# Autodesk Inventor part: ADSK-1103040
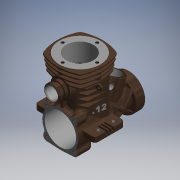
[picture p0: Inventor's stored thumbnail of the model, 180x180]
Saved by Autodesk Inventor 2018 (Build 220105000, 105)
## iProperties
Shininess: 11.0
Compacted: True
Length Units: 11269
Angle Units: 11279
Time Units: 11290
Mass Units: 11286
Length Display Precision: 2
Angle Display Precision: 2
Created: 2000-07
Part Number: ADSK-1103040
Document SubType Name: Modeling
Description: ENGINE  CASE - REAR
Mass: 106.427 g
Surface Area: 158.116 cm^2
Volume: 13.1716 cm^3
Density: 8.08 g/cm^3
Material: Stainless Steel
Appearance: Bronze - Satin
Density: 0.0
Volumn: 0.0
Area: 0.0
PropertySet Name: Model Information
Control State: 0
Master: False
Checked Out: False
Author: Autodesk, Inc.
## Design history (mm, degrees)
node "Extrusion1" dims "d2" = 3.5, "d3" = 0
  sketch "Sketch2"
    geometry: L1 (-28.715, -16.977)-(11.285, -16.977); L2 (11.285, -16.977)-(11.285, 3.023); L3 (11.285, 3.023)-(-28.715, 3.023); L4 (-28.715, 3.023)-(-28.715, -16.977)
    constraints: 8 end point, 2 parallel, 1 horizontal, 1 perpendicular
    dimensions: "d0" = 40 distance of L2.end L3.end; "d1" = 20 distance of L3.end L1.start
workplane "Work Plane1"
workplane "Work Plane2"
node "Extrusion2" dims "d6" = 25.5, "d7" = 0
  sketch "Sketch3"
    geometry: L1 (20, -16.8)-(20, 16.8) reference; L2 (0, 0)-(40, 0) reference; C1 r 12 at (20, 0)
    constraints: 1 centre point, 1 midpoint
    dimensions: "d5" = 24 diameter of C1
node "Extrusion3" dims "d13" = 25, "d14" = 0
  sketch "Sketch4"
    geometry: L1 (-20.715, 3.023)-(3.285, 3.023); L2 (-2.715, -16.977)-(-14.715, -16.977); L3 (-8.715, -21.506)-(-8.715, 7.111) reference; L4 (-28.715, -16.977)-(-20.715, -16.977) reference; A1 r 36.333 centre (-33.049, 3.023) between (-2.715, -16.977) and (3.285, 3.023); A2 r 36.333 centre (15.618, 3.023) between (-20.715, 3.023) and (-14.715, -16.977)
    constraints: 4 end point, 4 point on circle, 2 centre point, 2 point on line, 1 collinear, 1 horizontal
    dimensions: "d8" = 24 distance of L1.start L1.end; "d9" = 12 distance of L2.start L2.end; "d10" = 6 distance from line of L3 L2.start (= 0.5 x d9); "d11" = 12 distance from line of L1.end L3 (= 0.5 x d8); "d12" = 20 distance between parallel lines of L2 L1
node "Extrusion5" dims "d18" = 14, "d19" = 0
  sketch "Sketch6"
    geometry: C1 r 11.33 at (0, 0); C2 r 8 at (0, 0); C3 r 12 at (0, 0) reference
    constraints: 2 centre point, 1 coincident
    dimensions: "d17" = 16 diameter of C2
workplane "Work Plane15"
node "Extrusion6" dims "d21" = 6, "d22" = 0
  sketch "Sketch7"
    geometry: C1 r 7.5 at (0, 0); C2 r 11 at (0, 0)
    constraints: 2 centre point, 1 coincident
    dimensions: "d20" = 22 diameter of C2
fillet "Fillet48" dims "d248" = 2
fillet "Fillet53" dims "d264" = 2, "d265" = 1
feature "LoftSrf2" dims "d266" = 0, "d267" = 90 deg, "d268" = 0, "d269" = 90 deg
  node "Edges3"
  node "Edges4"
feature "OffsetSrf1" dims "d270" = 1, "d271" = 1
node "Revolution1" dims "d28" = 90 deg
  sketch "Sketch10"
    geometry: L1 (-20, -3.5)-(0, -3.5) reference; L2 (-20.351, 1.344)-(-25.14, 14.5); L3 (-25.14, 14.5)-(-31.718, 12.106); L4 (-31.718, 12.106)-(-26.929, -1.05); L5 (-26.929, -1.05)-(-20.351, 1.344); L6 (-22.5, 4.5)-(-36.5, 4.5) reference; L7 (-22.5, -15.5)-(-22.5, 8.5) reference; 1 further point
    constraints: 8 end point, 2 perpendicular, 2 point on line, 1 parallel
    dimensions: "d26" = 70 deg angle of L1 L2; "d27" = 14 diameter of L2 L4; "d231" = 14 distance of L2.start L2.end; "d241" = 10 distance from line of L6 L2.end; "d242" = 1 distance from line of L7 point (-21.5, 4.5)
workplane "Work Plane3"
  workaxis "Work Axis1"
workaxis "Work Axis2"
workplane "Work Plane5"
workplane "Work Plane30"
node "Extrusion12" dims "d54" = 8, "d55" = 0
  sketch "Sketch15"
    geometry: L1 (-9, 9)-(9, 9); L2 (9, 9)-(9, -9); L3 (9, -9)-(-9, -9); L4 (-9, -9)-(-9, 9); C1 r 12 at (0, 0) reference; C2 r 2.5 at (-9, 9); C3 r 2.5 at (9, 9); C4 r 2.5 at (9, -9); C5 r 2.5 at (-9, -9)
    constraints: 8 end point, 4 centre point, 4 coincident, 3 equal radius, 2 parallel, 2 perpendicular, 1 horizontal
    dimensions: "d50" = 18 distance of L2.end L3.end; "d51" = 9 distance from line of C1.centre L4 (= 0.5 x d50); "d52" = 9 distance from line of C1.centre L3 (= d51); "d53" = 5 diameter of C3
node "Extrusion13" dims "d56" = 8, "d57" = 0
  sketch "Sketch16"
    geometry: L1 (10.857, -11.496)-(19.314, -11.98); L2 (29.143, -11.496)-(20.686, -11.98); A1 r 2.5 centre (11, -9) between (10.039, -6.692) and (13.308, -9.961) reference; A2 r 12 centre (20, 0) between (13.308, -9.961) and (26.692, -9.961) reference; A3 r 2.5 centre (29, -9) between (26.692, -9.961) and (29.961, -6.692) reference
    constraints: 4 end point, 4 point on circle, 4 tangent
node "Fillet1" dims "d58" = 2.5
node "Fillet3" dims "d60" = 5
node "Fillet4" dims "d61" = 3
node "Fillet5" dims "d62" = 2
node "Revolution2" dims "d63" = 180 deg
  sketch "Sketch17"
    geometry: L1 (0.686, 11.98)-(9.143, 11.496) reference; L2 (9.143, 11.496)-(0.686, 11.98); L3 (0.686, 11.98)-(0.543, 9.484); L4 (0.543, 9.484)-(9, 9); L5 (9, 9)-(9.143, 11.496); L6 (9, 9)-(11.496, 8.857); A1 r 12 centre (0, 0) between (9.961, 6.692) and (0.686, 11.98) reference; A2 r 2.5 centre (9, 9) between (9.961, 6.692) and (9.143, 11.496) reference
    constraints: 10 end point, 3 equal length, 2 perpendicular, 2 tangent, 1 point on circle, 1 point on line
node "Mirror2"
node "Fillet6" dims "d64" = 2.5
node "Fillet8" dims "d66" = 3.5
node "Fillet17" dims "d75" = 2
node "Fillet18" dims "d76" = 0.3
node "Fillet19" dims "d77" = 0.5
node "Extrusion14" dims "d84" = 9, "d85" = 0
  sketch "Sketch18"
    geometry: L1 (-17.028, 3.023)-(-0.402, 3.023) reference; L2 (-8.715, -25.077)-(-8.715, 10.623) reference; C1 r 10.018 at (-8.715, -6.996); A1 r 36.333 centre (15.618, 3.023) between (-20.508, -0.85) and (-16.281, -14.371) reference
    constraints: 2 tangent, 1 centre point, 1 point on line
node "Extrusion15" dims "d90" = 1, "d91" = 0
  sketch "Sketch19"
    geometry: L1 (5.035, 6.754)-(-22.465, 6.754); L2 (-22.465, 6.754)-(-22.465, -20.746); L3 (-22.465, -20.746)-(5.035, -20.746); L4 (5.035, -20.746)-(5.035, 6.754); A1 r 10.018 centre (-8.715, -6.996) between (0.549, -10.81) and (-8.715, 3.023) reference; A2 r 27.5 centre (-22.465, -6.996) between (2.599, -18.31) and (2.599, 4.319); A3 r 27.5 centre (5.035, -6.996) between (-20.03, 4.319) and (-20.03, -18.31); A4 r 27.5 centre (-8.715, 6.754) between (-20.03, -18.31) and (2.599, -18.31); A5 r 27.5 centre (-8.715, -20.746) between (2.599, 4.319) and (-20.03, 4.319); A6 r 29.032 centre (-8.715, -20.746) between (-22.465, 4.823) and (-23.458, 4.264)
    constraints: 12 point on circle, 8 end point, 5 centre point, 3 midpoint, 3 tangent, 2 parallel, 2 perpendicular, 1 horizontal, 1 point on line
    dimensions: "d86" = 27.5 distance of L2.end L3.end; "d87" = 13.75 distance from line of L4 A1.centre (= 0.5 x d86); "d88" = 13.75 distance from line of L3 A1.centre (= d87); "d89" = 13.75 distance from line of L2 A4.centre (= d87)
node "Fillet26" dims "d92" = 2
workplane "Work Plane6"
node "Extrusion16" dims "d95" = 1, "d96" = 0
  sketch "Sketch20"
    geometry: A1 r 27.5 centre (-8.715, -20.746) between (1.847, 4.645) and (-19.278, 4.645) reference; A2 r 27.5 centre (5.035, -6.996) between (-20.356, 3.567) and (-20.356, -17.558) reference; A3 r 2 centre (-18.509, 2.798) between (-19.278, 4.645) and (-20.356, 3.567) reference; A4 r 2 centre (1.079, 2.798) between (2.925, 3.567) and (1.847, 4.645) reference; A5 r 27.5 centre (-22.465, -6.996) between (2.925, -17.558) and (2.925, 3.567) reference; A6 r 2 centre (1.079, -16.79) between (1.847, -18.636) and (2.925, -17.558) reference; A7 r 27.5 centre (-8.715, 6.754) between (-19.278, -18.636) and (1.847, -18.636) reference; A8 r 2 centre (-18.509, -16.79) between (-20.356, -17.558) and (-19.278, -18.636) reference; A9 r 28 centre (-8.715, -20.746) between (2.039, 5.107) and (-19.47, 5.107); A10 r 2.5 centre (1.079, 2.798) between (3.387, 3.759) and (2.039, 5.107); A11 r 28 centre (-22.465, -6.996) between (3.387, -17.75) and (3.387, 3.759); A12 r 2.5 centre (1.079, -16.79) between (2.039, -19.098) and (3.387, -17.75); A13 r 28 centre (-8.715, 6.754) between (-19.47, -19.098) and (2.039, -19.098); A14 r 2.5 centre (-18.509, -16.79) between (-20.818, -17.75) and (-19.47, -19.098); A15 r 28 centre (5.035, -6.996) between (-20.818, 3.759) and (-20.818, -17.75); A16 r 2.5 centre (-18.509, 2.798) between (-19.47, 5.107) and (-20.818, 3.759)
    constraints: 16 point on circle, 8 centre point, 7 other
    dimensions: "d94" = 0.5 radial gap between concentric circles of A9 A1
workplane "Work Plane7"
node "Extrusion17" dims "d99" = 1, "d100" = 0
  sketch "Sketch21"
    geometry: A1 r 28 centre (-8.715, -20.746) between (2.039, 5.107) and (-19.47, 5.107) reference; A2 r 28 centre (5.035, -6.996) between (-20.818, 3.759) and (-20.818, -17.75) reference; A3 r 2.5 centre (-18.509, -16.79) between (-20.818, -17.75) and (-19.47, -19.098) reference; A4 r 2.5 centre (-18.509, 2.798) between (-19.47, 5.107) and (-20.818, 3.759) reference; A5 r 28 centre (-8.715, 6.754) between (-19.47, -19.098) and (2.039, -19.098) reference; A6 r 2.5 centre (1.079, -16.79) between (2.039, -19.098) and (3.387, -17.75) reference; A7 r 28 centre (-22.465, -6.996) between (3.387, -17.75) and (3.387, 3.759) reference; A8 r 2.5 centre (1.079, 2.798) between (3.387, 3.759) and (2.039, 5.107) reference; A9 r 28.5 centre (-8.715, -20.746) between (2.231, 5.568) and (-19.662, 5.568); A10 r 3 centre (1.079, 2.798) between (3.849, 3.951) and (2.231, 5.568); A11 r 28.5 centre (-22.465, -6.996) between (3.849, -17.942) and (3.849, 3.951); A12 r 3 centre (1.079, -16.79) between (2.231, -19.56) and (3.849, -17.942); A13 r 28.5 centre (-8.715, 6.754) between (-19.662, -19.56) and (2.231, -19.56); A14 r 3 centre (-18.509, -16.79) between (-21.279, -17.942) and (-19.662, -19.56); A15 r 28.5 centre (5.035, -6.996) between (-21.279, 3.951) and (-21.279, -17.942); A16 r 3 centre (-18.509, 2.798) between (-19.662, 5.568) and (-21.279, 3.951)
    constraints: 16 point on circle, 8 centre point, 7 other
    dimensions: "d98" = 0.5 radial gap between concentric circles of A9 A1
workplane "Work Plane8"
node "Extrusion18" dims "d103" = 1, "d104" = 0
  sketch "Sketch22"
    geometry: A1 r 28.5 centre (-8.715, -20.746) between (2.231, 5.568) and (-19.662, 5.568) reference; A2 r 3 centre (-18.509, 2.798) between (-19.662, 5.568) and (-21.279, 3.951) reference; A3 r 28.5 centre (5.035, -6.996) between (-21.279, 3.951) and (-21.279, -17.942) reference; A4 r 3 centre (-18.509, -16.79) between (-21.279, -17.942) and (-19.662, -19.56) reference; A5 r 28.5 centre (-8.715, 6.754) between (-19.662, -19.56) and (2.231, -19.56) reference; A6 r 3 centre (1.079, -16.79) between (2.231, -19.56) and (3.849, -17.942) reference; A7 r 28.5 centre (-22.465, -6.996) between (3.849, -17.942) and (3.849, 3.951) reference; A8 r 3 centre (1.079, 2.798) between (3.849, 3.951) and (2.231, 5.568) reference; A9 r 29 centre (-8.715, -20.746) between (2.423, 6.03) and (-19.854, 6.03); A10 r 3.5 centre (1.079, 2.798) between (4.31, 4.143) and (2.423, 6.03); A11 r 29 centre (-22.465, -6.996) between (4.31, -18.134) and (4.31, 4.143); A12 r 3.5 centre (1.079, -16.79) between (2.423, -20.021) and (4.31, -18.134); A13 r 29 centre (-8.715, 6.754) between (-19.854, -20.021) and (2.423, -20.021); A14 r 3.5 centre (-18.509, -16.79) between (-21.741, -18.134) and (-19.854, -20.021); A15 r 29 centre (5.035, -6.996) between (-21.741, 4.143) and (-21.741, -18.134); A16 r 3.5 centre (-18.509, 2.798) between (-19.854, 6.03) and (-21.741, 4.143)
    constraints: 16 point on circle, 8 centre point, 7 other
    dimensions: "d102" = 0.5 radial gap between concentric circles of A9 A1
node "Extrusion19" dims "d108" = 1, "d109" = 0
  sketch "Sketch23" dims "d105" = 23
    geometry: L1 (-8.715, -31.799)-(-8.715, 35.076) reference; C1 r 10.018 at (-8.715, -6.996) reference; A1 r 2 centre (-8.715, 4.504) between (-6.717, 4.422) and (-10.714, 4.422); A2 r 2 centre (-4.719, 4.339) between (-6.717, 4.422) and (-5.384, 2.453); A3 r 2 centre (-12.712, 4.339) between (-12.047, 2.453) and (-10.714, 4.422); A4 r 10.018 centre (-8.715, -6.996) between (-5.384, 2.453) and (-12.047, 2.453); 1 further point
    constraints: 8 point on circle, 4 centre point, 4 tangent, 2 equal radius, 1 coincident, 1 concentric, 1 point on line, 1 vertical alignment, 2 other
    dimensions: "d106" = 4 diameter of A1; "d107" = 2 radius of A2
workaxis "Work Axis3"
node "Circular Pattern2" dims "d110" = 40, "d112" = 360 deg
node "Fillet27" dims "d113" = 0.3
node "Fillet28" dims "d114" = 0.5
workplane "Work Plane9"
node "Fillet34" dims "d130" = 0.45
sketch "Sketch47"
  geometry: L1 (0, 8.296)-(0, -10.725)
  constraints: 2 end point, 1 vertical
feature "Rib1" sketch "Sketch47" dims "d246" = 2, "d247" = 1
fillet "Fillet49" dims "d249" = 1
fillet "Fillet50" dims "d250" = 1
fillet "Fillet51" dims "d251" = 1
fillet "Fillet52" dims "d252" = 1
workplane "Work Plane17"
split "Split2"
sketch "Sketch51"
  geometry: L1 (-37.441, 3.747)-(-20.441, -10.747); L2 (-37.441, -10.747)-(-20.441, 3.747); L3 (-37.441, 4.569)-(-37.441, 2.926); L4 (-37.441, 2.926)-(-29.905, -3.5); L5 (-29.905, -3.5)-(-37.441, -9.926); L6 (-37.441, -9.926)-(-37.441, -11.569); L7 (-37.441, -11.569)-(-28.941, -4.321); L8 (-28.941, -4.321)-(-20.441, -11.569); L9 (-20.441, -11.569)-(-20.441, -9.926); L10 (-20.441, -9.926)-(-27.978, -3.5); L11 (-27.978, -3.5)-(-20.441, 2.926); L12 (-20.441, 2.926)-(-20.441, 4.569); L13 (-20.441, 4.569)-(-28.941, -2.679); L14 (-28.941, -2.679)-(-37.441, 4.569); L15 (-37.441, -13.502)-(-37.441, 6.502) reference; L16 (-20.441, -14.502)-(-20.441, 7.502) reference; 2 further points
  constraints: 28 end point, 12 collinear, 8 parallel, 6 midpoint, 2 horizontal alignment, 1 vertical
  dimensions: "d272" = 1.25 distance between parallel lines of L14 L4
extrude "Extrusion38" join sketch "Sketch51" stored distance "d273" = 14; taper "d274" = 0 deg
mirror "Mirror3"
fillet "Fillet54" dims "d275" = 1
fillet "Fillet58" dims "d279" = 10
fillet "Fillet55" dims "d276" = 0.3
fillet "Fillet57" dims "d278" = 0.3
node "Hole1" dims "d139" = 2.013, "d140" = 4, "d141" = 2, "d142" = 60 deg, "d143" = 5, "d144" = 118 deg
  sketch "Sketch28"
    geometry: A1 r 2.5 centre (29, 9) between (30.967, 7.457) and (27.457, 10.967) reference; A2 r 2.5 centre (11, 9) between (12.543, 10.967) and (9.033, 7.457) reference; A3 r 2.5 centre (11, -9) between (8.939, -7.585) and (10.857, -11.496) reference; A4 r 2.5 centre (29, -9) between (29.143, -11.496) and (31.061, -7.585) reference
node "Extrusion24" dims "d152" = 25, "d153" = 0
  sketch "Sketch30"
    geometry: C1 r 9 at (-8.715, -6.996); A1 r 10.518 centre (-8.715, -6.996) between (-18.635, -10.493) and (-12.213, -16.915) reference
    constraints: 1 centre point, 1 coincident
    dimensions: "d151" = 18 diameter of C1
node "Extrusion25" dims "d154" = 0.25, "d155" = 0
  sketch "Sketch31"
    geometry: C1 r 9 at (-8.715, -6.996) reference; A1 r 28.7 centre (-8.715, 6.754) between (-19.739, -19.744) and (2.308, -19.744) reference; 1 further point
    constraints: 1 coincident, 1 vertical alignment, 2 other
workaxis "Work Axis8"
workplane "Work Plane33"
node "Fillet38" dims "d156" = 0.5
node "Hole3" dims "d157" = 2.013, "d158" = 4, "d159" = 2, "d160" = 60 deg, "d161" = 8, "d162" = 118 deg
  sketch "Sketch32"
    geometry: A1 r 2.5 centre (-8.715, 4.504) between (-6.218, 4.401) and (-11.213, 4.401) reference; 2 further points
node "Circular Pattern3" dims "d163" = 40, "d165" = 360 deg
workplane "Work Plane10"
node "Extrusion26" dims "d172" = 1, "d173" = 0
  sketch "Sketch33"
    geometry: L1 (20.526, -0.599)-(20.124, -12.117); L2 (18.879, -14.443)-(13.845, -16.58); L3 (15.656, -15.268)-(18.907, -13.888); L4 (0.402, 3.023)-(17.028, 3.023) reference; A1 r 36.333 centre (-15.618, 3.023) between (16.281, -14.371) and (20.508, -0.85) reference; A2 r 3.5 centre (17.028, -0.477) between (20.508, -0.85) and (17.028, 3.023) reference; A3 r 5 centre (11.892, -11.977) between (11.892, -16.977) and (16.281, -14.371) reference; A4 r 2 centre (18.125, -12.047) between (18.907, -13.888) and (20.124, -12.117)
    constraints: 6 end point, 5 point on circle, 4 tangent, 1 centre point, 1 parallel
    dimensions: "d168" = 115 deg angle of L2 L1; "d170" = 2 radius of A4; "d171" = 0.5 distance between parallel lines of L2 L3; "d280" = 88 deg angle of L4 L1
node "Fillet39" dims "d174" = 0.3
mirror "Mirror4"
fillet "Fillet59" dims "d281" = 0.5
node "Rectangular Pattern1" dims "d176" = 40, "d178" = 3.5
node "Extrusion27" dims "d180" = 4, "d181" = 0
  sketch "Sketch34"
    geometry: C1 r 11 at (0, 0); C2 r 8 at (0, 0); A1 r 11 centre (0, 0) between (-11, 0) and (11, 0) reference; A2 r 11 centre (0, 0) between (11, 0) and (-11, 0) reference
    constraints: 2 centre point, 1 coincident
    dimensions: "d179" = 16 diameter of C2
node "Extrusion28" dims "d183" = 4, "d184" = 0
  sketch "Sketch35"
    geometry: C1 r 8 at (0, 0) reference; C2 r 6 at (0, 0)
    constraints: 1 centre point, 1 coincident
    dimensions: "d182" = 12 diameter of C2
node "Extrusion29" dims "d186" = 20, "d187" = 0
  sketch "Sketch36"
    geometry: C1 r 10.5 at (20, 0); A1 r 12 centre (20, 0) between (30.859, -5.106) and (30.749, 5.334) reference
    constraints: 1 centre point, 1 coincident
    dimensions: "d185" = 21 diameter of C1
node "Extrusion30" dims "d189" = 22, "d190" = 0
  sketch "Sketch37"
    geometry: C1 r 7 at (-8.715, -6.996); A1 r 13.75 centre (-8.715, -6.996) between (5.035, -6.996) and (-22.465, -6.996) reference
    constraints: 1 centre point, 1 coincident
    dimensions: "d188" = 14 diameter of C1
sketch "Sketch43"
  geometry: L1 (12.324, 33.859)-(-10.939, -30.056); L2 (1.197, 3.289)-(-5.381, 5.683); L3 (-4.342, 9.03)-(5.376, 5.493); L4 (17.596, 48.345)-(-18.614, -51.141) reference; L5 (-8.665, 10.603)-(-8.323, 10.479) reference; L6 (-8.323, 10.479)-(-4.885, 9.227) reference; L7 (-3.975, 8.896)-(-4.885, 9.227) reference; L8 (-3.975, 8.896)-(-3.975, 8.896) reference; L9 (-4.885, 9.227)-(-3.975, 8.896) reference; L10 (-4.885, 9.227)-(-8.323, 10.479) reference; L11 (-8.665, 10.603)-(-8.323, 10.479) reference; C1 r 2.75 at (-5.381, 5.683)
  constraints: 6 end point, 2 collinear, 1 centre point, 1 coincident, 1 perpendicular, 1 point on line
  dimensions: "d216" = 7 distance of L2.start L2.end; "d217" = 3.5 distance between parallel lines of L2 L3; "d218" = 5.5 diameter of C1
extrude "Extrusion39" join sketch "Sketch43" distance "d282" = 14; taper "d283" = 0 deg
fillet "Fillet60" dims "d284" = 0.5
node "Extrusion35" dims "d223" = 15, "d224" = 0
  sketch "Sketch44"
    geometry: C1 r 5.5 at (0, 0); A1 r 7 centre (0, 0) between (1.75, -6.778) and (-1.75, -6.778) reference
    constraints: 1 centre point, 1 concentric
    dimensions: "d222" = 11 diameter of C1
node "Extrusion36" dims "d226" = 15, "d227" = 0
  sketch "Sketch45"
    geometry: C1 r 2.75 at (0, 0); C2 r 2 at (0, 0); C3 r 2.75 at (0, 0) reference
    constraints: 2 centre point, 1 coincident
    dimensions: "d225" = 4 diameter of C2
node "Chamfer1" dims "d228" = 0.5, "d229" = 0.5, "d239" = 45 deg
node "Hole4" dims "d233" = 2.5, "d234" = 4, "d235" = 2, "d236" = 60 deg, "d237" = 8, "d238" = 118 deg
  sketch "Sketch46"
    geometry: C1 r 1.078 at (8.285, -11.027) reference; C2 r 1.078 at (8.285, -1.027) reference; C3 r 1.078 at (-25.715, -1.977) reference; C4 r 1.078 at (-25.715, -11.977) reference
sketch "Sketch52"
  geometry: L1 (1.337, 11.656)-(8.684, 11.656); L2 (8.684, 11.656)-(8.684, 8.517); L3 (8.684, 8.517)-(1.337, 8.517); L4 (1.337, 8.517)-(1.337, 11.656)
  constraints: 2 other
emboss "Emboss1" sketch "Sketch52" dims "d288" = 0.333, "d289" = 0
sketch "Sketch53"
  geometry: L1 (-11.887, 5.713)-(-11.887, 13.872); L2 (-11.887, 13.872)-(-8.327, 13.872); L3 (-8.327, 13.872)-(-8.327, 5.713); L4 (-8.327, 5.713)-(-11.887, 5.713)
  constraints: 2 other
emboss "Emboss2" sketch "Sketch53" dims "d293" = 0.33, "d294" = 0
fillet "Fillet77" dims "d396" = 0.25
fillet "Fillet78" dims "d397" = 0.1
fillet "Fillet79" dims "d398" = 0.25
fillet "Fillet80" dims "d399" = 0.1
split "Split4"
split "Split7"
sketch "Sketch54"
  geometry: L1 (-37.441, -13.502)-(-20.441, -14.502) reference; L2 (-34.186, -13.693)-(-24.164, -14.283); L3 (11.1, -3.5)-(-45.6, -3.5) reference; A1 r 1 centre (-37.5, -13.5) between (-37.5, -14.5) and (-36.5, -13.5) reference; A2 r 2 centre (-20.5, -13.5) between (-22.5, -13.5) and (-20.5, -15.5) reference; A3 r 1 centre (-37.5, -13.5) between (-37.5, -14.5) and (-36.997, -14.364); A4 r 2 centre (-20.5, -13.5) between (-21.631, -15.15) and (-20.5, -15.5); A5 r 5 centre (-34.48, -18.685) between (-34.186, -13.693) and (-36.997, -14.364); A6 r 5 centre (-24.457, -19.274) between (-21.631, -15.15) and (-24.164, -14.283)
  constraints: 10 point on circle, 5 tangent, 4 centre point, 3 equal radius, 2 end point, 1 collinear, 1 point on line
  dimensions: "d295" = 5 radius of A5
feature "RevolutionSrf1" sketch "Sketch54" dims angle "d328" = 10 deg
thicken "Thicken1" dims "d329" = 3, "d330" = 4
node "Extrusion31" dims "d192" = 5, "d193" = 0
  sketch "Sketch38"
    geometry: C1 r 10.5 at (0, 0) reference; C2 r 9.5 at (0, 0)
    constraints: 1 centre point, 1 coincident
    dimensions: "d191" = 19 diameter of C2
fillet "Fillet64" dims "d331" = 0.5
fillet "Fillet65" dims "d332" = 0.5
workplane "Work Plane29"
workplane "Work Plane31"
workaxis "Work Axis7"
sketch "Sketch55"
  geometry: C1 r 6.5 at (0, 23.5); 1 further point
  constraints: 1 centre point, 1 coincident
  dimensions: "d336" = 13 diameter of C1
extrude "Extrusion40" join sketch "Sketch55" stored distance "d337" = 10; taper "d338" = 0 deg
sketch "Sketch57"
  geometry: L1 (2.25, 9.25)-(2.25, 8.75); L2 (3, 1.834)-(3, -8.606) reference; L3 (3, 8.5)-(2, 8.5) reference
  constraints: 2 end point, 1 vertical
  dimensions: "d389" = 0.75 distance between parallel lines of L2 L1; "d390" = 0.25 distance from line of L3 L1.end; "d391" = 0.5 distance of L1.start L1.end
feature "Rib5" sketch "Sketch57" dims "d341" = 1, "d342" = 2
fillet "Fillet66" dims "d343" = 0.5
fillet "Fillet67" dims "d394" = 0.4
fillet "Fillet68" dims "d347" = 0.5
sketch "Sketch58"
  geometry: C1 r 6.5 at (0, 0) reference; C2 r 5.25 at (0, 0); C3 r 7.516 at (0, 0); 2 further points
  constraints: 2 centre point, 2 coincident, 1 horizontal alignment
  dimensions: "d348" = 1.25 radial gap between concentric circles of C2 C1
extrude "Extrusion41" cut sketch "Sketch58" distance "d349" = 6 (derived); taper "d350" = 0 deg
hole "Hole5" diameter "d353" = 8; stored, may be unused: countersink angle "d357" = 90 deg, drill point angle "d359" = 118 deg; dims "d351" = 10, "d352" = 10, "d354" = 6, "d355" = 4, "d356" = 2, "d358" = 8
chamfer "Chamfer2" distance "d360" = 0.5; stored, may be unused: second distance "d361" = 2, angle "d362" = 45 deg
fillet "Fillet76" dims "d393" = 0.5
sketch "Sketch59"
  geometry: L1 (12.125, 12.4)-(12.125, 12.5); L2 (15.875, 12.5)-(15.875, 12.4); A1 r 1.875 centre (14, 12.5) between (15.875, 12.5) and (12.125, 12.5); 1 further point
  constraints: 4 end point, 2 parallel, 2 point on circle, 2 tangent, 1 centre point, 1 vertical, 1 vertical alignment
  dimensions: "d364" = 1.875 radius of A1; "d365" = 12.5 distance of point (14, 0) A1.centre; "d366" = 0.1 distance of L1.start L1.end
extrude "Extrusion42" join sketch "Sketch59" distance "d368" = 1.5; taper "d369" = 0 deg
hole "Hole6" diameter "d372" = 1.5; stored, may be unused: countersink angle "d376" = 90 deg, drill point angle "d378" = 118 deg; dims "d370" = 10, "d371" = 10, "d373" = 6, "d374" = 4, "d375" = 2, "d377" = 8
fillet "Fillet69" dims "d379" = 0.5
mirror "Mirror5"
fillet "Fillet70" dims "d380" = 0.5
fillet "Fillet71" dims "d381" = 0.3
workplane "Work Plane34"
sketch "Sketch60"
  geometry: L1 (11.964, 9.428)-(11.964, 10.362); L2 (11.964, 10.362)-(29.739, 10.362); L3 (-10.2, 0)-(59.45, 0) reference
  constraints: 4 end point, 1 parallel, 1 perpendicular, 1 vertical
revolve "Revolution3" sketch "Sketch60" stored, may be unused: angle "d384" = 45 deg
fillet "Fillet72" dims "d385" = 2
fillet "Fillet73" dims "d386" = 1
mirror "Mirror6"
fillet "Fillet74" dims "d387" = 2
fillet "Fillet75" dims "d388" = 1
sketch "Sketch61" dims "d405" = 10
  geometry: L1 (3.2, 16)-(3.2, 0) reference; L2 (3.5, 10.482)-(1.5, 10.482); L3 (1.5, 10.482)-(1.5, 9.482); L4 (1.5, 9.482)-(3.5, 9.482); L5 (3.5, 9.482)-(3.5, 10.482); L6 (3.5, 8.482)-(1.5, 8.482); L7 (1.5, 8.482)-(1.5, 7.482); L8 (1.5, 7.482)-(3.5, 7.482); L9 (3.5, 7.482)-(3.5, 8.482); L10 (3.5, 6.482)-(1.5, 6.482); L11 (1.5, 6.482)-(1.5, 5.482); L12 (1.5, 5.482)-(3.5, 5.482); L13 (3.5, 5.482)-(3.5, 6.482); L14 (47.7, 7.982)-(-21.95, 7.982) reference; L15 (3.5, 0)-(3.5, 16) reference
  constraints: 24 end point, 6 parallel, 3 perpendicular, 1 collinear, 1 horizontal, 1 vertical, 17 other
  dimensions: "d402" = 2 distance of L2.start L6.start; "d407" = 1 distance of L4.end L2.start; "d408" = 2 distance of L2.start L2.end
extrude "Extrusion43" cut sketch "Sketch61" distance "d409" = 6; taper "d410" = 0 deg
fillet "Fillet81" dims "d411" = 0.5
mirror "Mirror7"
sketch "Sketch62"
  geometry: L1 (8.5, 25.25)-(3, 25.25) reference; L2 (3, 23.411)-(3, 13.5) reference; L3 (5, 25.25)-(6.5, 25.25); L4 (6.5, 25.25)-(6.5, 24.5); L5 (6.5, 24.5)-(5, 24.5); L6 (5, 24.5)-(5, 25.25); L7 (9, 24.75)-(9, 15.25) reference; L8 (9, 20)-(8.345, 20)
  constraints: 10 end point, 2 parallel, 2 perpendicular, 1 horizontal, 1 midpoint, 1 point on line
  dimensions: "d422" = 0.75 distance of L3.end L4.end; "d423" = 1.5 distance between parallel lines of L4 L6; "d424" = 2.5 distance between parallel lines of L7 L4
revolve "Revolution4" sketch "Sketch62" stored, may be unused: angle "d425" = 90 deg
workplane "Work Plane35"
body "Solid1"
body "Srf1"
body "Srf2"
node "Projected Loop1"
body "Srf3"
other parameters: "d4" = 3, "d37" = 45 deg, "d93" = 2, "d97" = 2, "d101" = 2, "d115" = -15, "d166" = 2, "d240" = 14, "d259" = 0, "d333" = 9, "d334" = 0, "d335" = 23.5, "d345" = 0, "d367" = 1.5, "d383" = 30 deg, "d418" = 40 deg, "d421" = 0
